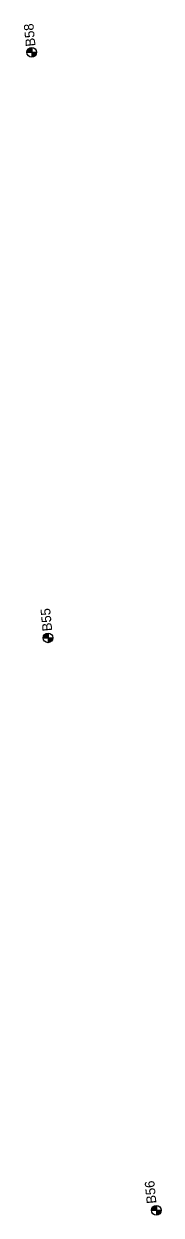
# Model space of a CAD drawing. Extents: x 345549 to 379569, y 127949 to 230467.
# Drawn here: x 360111 to 360253, y 159931 to 161160 of the extents above; entities that cross this region are included whole.
import ezdxf

# ---------------------------------------------------------------- set-up
doc = ezdxf.new("R2010")
doc.units = 0
doc.layers.add('E_SOIL_BORE2 [KAPUR_CADDS_LEVELS]', color=7, linetype='Continuous')
doc.layers.add('P_MARK', color=7, linetype='Continuous')

msp = doc.modelspace()

# ---------------------------------------------------------------- linework, layer by layer
at = {"layer": 'P_MARK'}
for p, q in [((360114.5, 161131), (360124.5, 161131)), ((360119.5, 161136), (360119.5, 161126)), ((360131.3, 160526.6), (360141.3, 160526.6)), ((360136.3, 160531.6), (360136.3, 160521.6)), ((360243.3, 159935.8), (360253.3, 159935.8)), ((360248.3, 159940.8), (360248.3, 159930.8))]:
    msp.add_line(p, q, dxfattribs=at)
for centre in [(360119.5, 161131), (360136.3, 160526.6), (360248.3, 159935.8)]:
    msp.add_circle(centre, 5, dxfattribs=at)
for centre, radius, start, end in [((360119.5, 161131), 4.5, 89.9869, 179.9869), ((360119.5, 161131), 4, 89.9869, 179.9869), ((360119.5, 161131), 3.5, 89.9869, 179.9869), ((360119.5, 161131), 3, 89.9869, 179.9869), ((360119.5, 161131), 2.5, 89.9869, 179.9869), ((360119.5, 161131), 2, 89.9869, 179.9869), ((360119.5, 161131), 1.5, 89.9869, 179.9869), ((360119.5, 161131), 1, 89.9869, 179.9869), ((360119.5, 161131), 0.5, 89.9869, 179.9869), ((360119.5, 161131), 4.5, 269.9869, 359.9869), ((360119.5, 161131), 4, 269.9869, 359.9869), ((360119.5, 161131), 3.5, 269.9869, 359.9869), ((360119.5, 161131), 3, 269.9869, 359.9869), ((360119.5, 161131), 2.5, 269.9869, 359.9869), ((360119.5, 161131), 2, 269.9869, 359.9869), ((360119.5, 161131), 1.5, 269.9869, 359.9869), ((360119.5, 161131), 1, 269.9869, 359.9869), ((360119.5, 161131), 0.5, 269.9869, 359.9869), ((360136.3, 160526.6), 4.5, 89.9869, 179.9869), ((360136.3, 160526.6), 4, 89.9869, 179.9869), ((360136.3, 160526.6), 3.5, 89.9869, 179.9869), ((360136.3, 160526.6), 3, 89.9869, 179.9869), ((360136.3, 160526.6), 2.5, 89.9869, 179.9869), ((360136.3, 160526.6), 2, 89.9869, 179.9869), ((360136.3, 160526.6), 1.5, 89.9869, 179.9869), ((360136.3, 160526.6), 1, 89.9869, 179.9869), ((360136.3, 160526.6), 0.5, 89.9869, 179.9869), ((360136.3, 160526.6), 4.5, 269.9869, 359.9869), ((360136.3, 160526.6), 4, 269.9869, 359.9869), ((360136.3, 160526.6), 3.5, 269.9869, 359.9869), ((360136.3, 160526.6), 3, 269.9869, 359.9869), ((360136.3, 160526.6), 2.5, 269.9869, 359.9869), ((360136.3, 160526.6), 2, 269.9869, 359.9869), ((360136.3, 160526.6), 1.5, 269.9869, 359.9869), ((360136.3, 160526.6), 1, 269.9869, 359.9869), ((360136.3, 160526.6), 0.5, 269.9869, 359.9869), ((360248.3, 159935.8), 4.5, 89.9869, 179.9869), ((360248.3, 159935.8), 4, 89.9869, 179.9869), ((360248.3, 159935.8), 3.5, 89.9869, 179.9869), ((360248.3, 159935.8), 3, 89.9869, 179.9869), ((360248.3, 159935.8), 2.5, 89.9869, 179.9869), ((360248.3, 159935.8), 2, 89.9869, 179.9869), ((360248.3, 159935.8), 1.5, 89.9869, 179.9869), ((360248.3, 159935.8), 1, 89.9869, 179.9869), ((360248.3, 159935.8), 0.5, 89.9869, 179.9869), ((360248.3, 159935.8), 4.5, 269.9869, 359.9869), ((360248.3, 159935.8), 4, 269.9869, 359.9869), ((360248.3, 159935.8), 3.5, 269.9869, 359.9869), ((360248.3, 159935.8), 3, 269.9869, 359.9869), ((360248.3, 159935.8), 2.5, 269.9869, 359.9869), ((360248.3, 159935.8), 2, 269.9869, 359.9869), ((360248.3, 159935.8), 1.5, 269.9869, 359.9869), ((360248.3, 159935.8), 1, 269.9869, 359.9869), ((360248.3, 159935.8), 0.5, 269.9869, 359.9869)]:
    msp.add_arc(centre, radius, start, end, dxfattribs=at)

# ---------------------------------------------------------------- texts
at = {"layer": 'E_SOIL_BORE2 [KAPUR_CADDS_LEVELS]'}
for s, p in [('B58', (360123.4, 161137.4)), ('B55', (360140.7, 160533.9)), ('B56', (360248.4, 159943.1))]:
    msp.add_text(s, height=10, rotation=95.5802, dxfattribs=at).set_placement(p)

doc.saveas('drawing.dxf')
